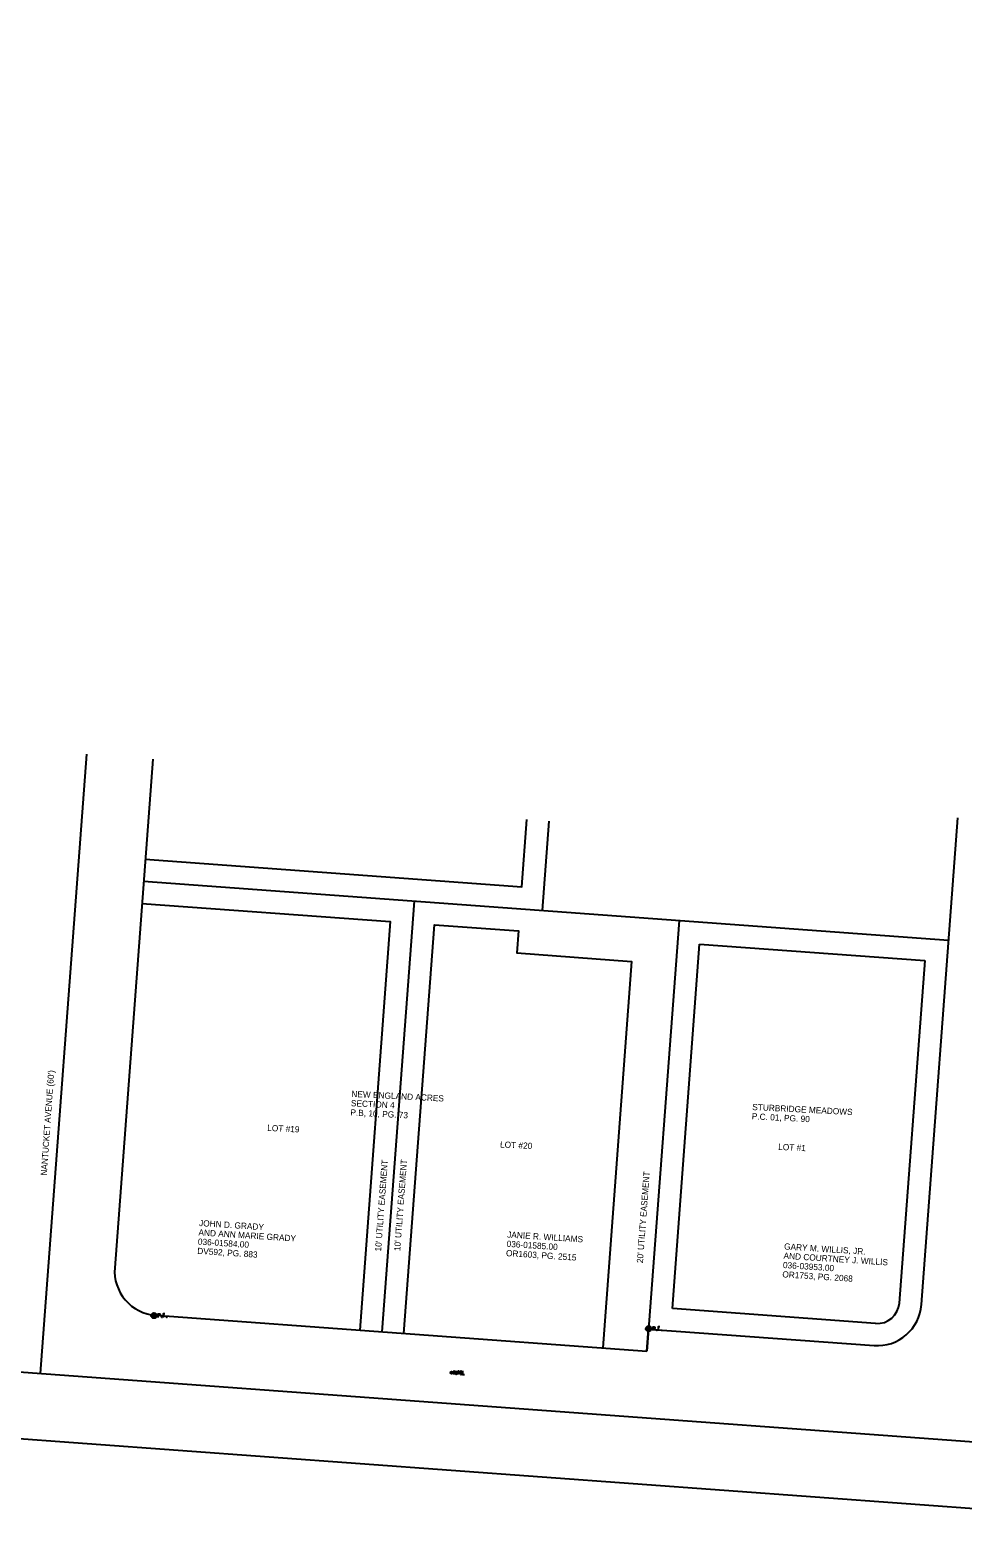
# Model space of a CAD drawing. Extents: x 1898254 to 1901377, y 701554 to 704886.
# Drawn here: x 1900647 to 1901068, y 703095 to 703775 of the extents above; entities that cross this region are included whole.
import ezdxf

# ---------------------------------------------------------------- set-up
doc = ezdxf.new("R2010")
doc.units = 0
for name, color, linetype in [('DV_X_Property_Line', 7, 'Continuous'), ('DV_X_Text', 7, 'Continuous'), ('RW_X_CL', 7, 'Continuous'), ('RW_X_Esmt_SH', 7, 'Continuous'), ('RW_X_Esmt_U', 7, 'Continuous'), ('RW_X_Fee_RW', 7, 'Continuous'), ('RW_X_Text', 7, 'Continuous'), ('SC_Scratch2', 7, 'Continuous'), ('SC_Scratch5', 7, 'Continuous'), ('SV_X_Control_Cells_Found', 7, 'Continuous'), ('SV_X_Mon_Cells_Found', 7, 'Continuous')]:
    doc.layers.add(name, color=color, linetype=linetype)

msp = doc.modelspace()

# ---------------------------------------------------------------- linework, layer by layer
at = {"layer": 'DV_X_Property_Line'}
for p, q in [((1900881.34, 703418.11), (1900878.32, 703377.77)), ((1900698.38, 703390.92), (1901061.83, 703364.35)), ((1900820.48, 703382), (1900805.96, 703187.54)), ((1900940.16, 703373.25), (1900925.64, 703178.79))]:
    msp.add_line(p, q, dxfattribs=at)
at = {"layer": 'RW_X_CL'}
for p, q in [((1900672.58, 703448.26), (1900651.7, 703168.73)), ((1899815.76, 703229.84), (1901162.17, 703131.42))]:
    msp.add_line(p, q, dxfattribs=at)
at = {"layer": 'RW_X_Esmt_SH'}
msp.add_line((1900608.03, 703141.85), (1901159.98, 703101.5), dxfattribs=at)
at = {"layer": 'RW_X_Esmt_U'}
for p, q in [((1900937.1, 703198), (1900949.39, 703362.55)), ((1900949.39, 703362.55), (1901051.12, 703355.11)), ((1901051.12, 703355.11), (1901039.57, 703200.52)), ((1901028.87, 703191.3), (1900937.1, 703198)), ((1901028.87, 703191.3), (1901028.87, 703191.3))]:
    msp.add_line(p, q, dxfattribs=at)
for points in [[(1900699.11, 703400.89), (1900869.1, 703388.47), (1900871.36, 703418.85)], [(1900697.65, 703380.95), (1900809.76, 703372.75), (1900795.98, 703188.27)], [(1900815.93, 703186.81), (1900829.71, 703371.29), (1900867.61, 703368.52), (1900866.86, 703358.55), (1900918.72, 703354.76), (1900905.69, 703180.25)]]:
    msp.add_lwpolyline(points, dxfattribs=at)
msp.add_arc((1901029.6, 703201.27), 10, 265.81918, 355.7289, dxfattribs=at)
at = {"layer": 'RW_X_Fee_RW'}
for p, q in [((1900702.5, 703446.02), (1900685.35, 703216.44)), ((1901049.54, 703199.78), (1901065.96, 703419.55)), ((1900703.84, 703195), (1900925.64, 703178.79)), ((1900925.64, 703178.79), (1900926.38, 703188.76)), ((1900926.38, 703188.76), (1901028.14, 703181.32))]:
    msp.add_line(p, q, dxfattribs=at)
for centre, start, end in [((1900705.29, 703214.95), 175.7289, 265.81918), ((1901029.6, 703201.27), 265.81918, 355.7289)]:
    msp.add_arc(centre, 20, start, end, dxfattribs=at)
at = {"layer": 'SC_Scratch2'}
msp.add_circle((1899815.76, 703229.84), 1561.35, dxfattribs=at)
at = {"layer": 'SC_Scratch5'}
for p, q in [((1900702.5, 703446.02), (1900685.35, 703216.44)), ((1901049.54, 703199.78), (1901065.96, 703419.55)), ((1900703.84, 703195), (1900925.64, 703178.79)), ((1900925.64, 703178.79), (1900926.38, 703188.76)), ((1900926.38, 703188.76), (1901028.14, 703181.32)), ((1900608.03, 703141.85), (1901159.98, 703101.5))]:
    msp.add_line(p, q, dxfattribs=at)
for centre, start, end in [((1900705.29, 703214.95), 175.7289, 265.81918), ((1901029.6, 703201.27), 265.81918, 355.7289)]:
    msp.add_arc(centre, 20, start, end, dxfattribs=at)
at = {"layer": 'SV_X_Control_Cells_Found'}
for p, q in [((1900837.1, 703169.44), (1900837.8, 703168.73)), ((1900837.1, 703168.73), (1900837.8, 703169.44))]:
    msp.add_line(p, q, dxfattribs=at)
for points in [[(1900838.54, 703168.28), (1900838.54, 703169.88), (1900839.49, 703168.28), (1900839.49, 703169.88)], [(1900839.99, 703168.28), (1900840.49, 703169.88), (1900840.98, 703168.28)], [(1900840.86, 703168.65), (1900840.11, 703168.65)], [(1900841.49, 703169.88), (1900841.89, 703169.88)], [(1900841.49, 703168.28), (1900841.89, 703168.28)], [(1900841.69, 703168.28), (1900841.69, 703169.88)], [(1900842.39, 703169.88), (1900842.39, 703168.28), (1900843.26, 703168.28)]]:
    msp.add_lwpolyline(points, dxfattribs=at)
msp.add_circle((1900837.45, 703169.09), 0.5, dxfattribs=at)
at = {"layer": 'SV_X_Mon_Cells_Found'}
for points in [[(1900705.04, 703194.06), (1900705.04, 703195.66), (1900705.57, 703195.66), (1900705.63, 703195.64), (1900705.7, 703195.62), (1900705.74, 703195.59), (1900705.77, 703195.57), (1900705.82, 703195.51), (1900705.85, 703195.44), (1900705.87, 703195.34), (1900705.87, 703195.19), (1900705.86, 703195.14), (1900705.84, 703195.06), (1900705.79, 703194.98), (1900705.75, 703194.94), (1900705.72, 703194.91), (1900705.66, 703194.89), (1900705.57, 703194.88), (1900705.04, 703194.88)], [(1900706.69, 703194.27), (1900706.74, 703194.27), (1900706.77, 703194.25), (1900706.81, 703194.19), (1900706.81, 703194.13), (1900706.77, 703194.08), (1900706.74, 703194.06), (1900706.69, 703194.06), (1900706.65, 703194.08), (1900706.62, 703194.13), (1900706.62, 703194.19), (1900706.65, 703194.25), (1900706.69, 703194.27)], [(1900708.05, 703195.66), (1900707.29, 703195.66), (1900707.29, 703194.06)], [(1900707.29, 703194.88), (1900707.83, 703194.88)], [(1900708.84, 703194.27), (1900708.89, 703194.27), (1900708.92, 703194.25), (1900708.96, 703194.19), (1900708.96, 703194.13), (1900708.92, 703194.08), (1900708.89, 703194.06), (1900708.84, 703194.06), (1900708.8, 703194.08), (1900708.77, 703194.13), (1900708.77, 703194.19), (1900708.8, 703194.25), (1900708.84, 703194.27)], [(1900928.39, 703188.12), (1900928.39, 703189.72), (1900928.92, 703189.72), (1900928.97, 703189.7), (1900929.05, 703189.68), (1900929.08, 703189.65), (1900929.12, 703189.63), (1900929.16, 703189.56), (1900929.19, 703189.5), (1900929.22, 703189.4), (1900929.22, 703189.25), (1900929.21, 703189.2), (1900929.18, 703189.12), (1900929.14, 703189.04), (1900929.1, 703189), (1900929.06, 703188.97), (1900929.01, 703188.95), (1900928.92, 703188.93), (1900928.39, 703188.93)], [(1900930.03, 703188.33), (1900930.09, 703188.33), (1900930.12, 703188.3), (1900930.15, 703188.25), (1900930.15, 703188.19), (1900930.12, 703188.14), (1900930.09, 703188.12), (1900930.03, 703188.12), (1900930, 703188.14), (1900929.97, 703188.19), (1900929.97, 703188.25), (1900930, 703188.3), (1900930.03, 703188.33)], [(1900931.4, 703189.72), (1900930.64, 703189.72), (1900930.64, 703188.12)], [(1900930.64, 703188.93), (1900931.18, 703188.93)], [(1900932.18, 703188.33), (1900932.24, 703188.33), (1900932.27, 703188.3), (1900932.3, 703188.25), (1900932.3, 703188.19), (1900932.27, 703188.14), (1900932.24, 703188.12), (1900932.18, 703188.12), (1900932.15, 703188.14), (1900932.12, 703188.19), (1900932.12, 703188.25), (1900932.15, 703188.3), (1900932.18, 703188.33)]]:
    msp.add_lwpolyline(points, dxfattribs=at)
for centre, radius in [((1900703.05, 703194.86), 1.2), ((1900703.05, 703194.86), 0.495), ((1900926.39, 703188.92), 1.2), ((1900926.39, 703188.92), 0.495)]:
    msp.add_circle(centre, radius, dxfattribs=at)

# ---------------------------------------------------------------- texts
at = {"layer": 'DV_X_Text'}
for s, rotation, p in [('NEW ENGLAND ACRES', 357.09486, (1900792.14, 703293.59)), ('SECTION 4', 357.09486, (1900791.93, 703289.4)), ('STURBRIDGE MEADOWS', 357.09486, (1900973.12, 703287.66)), ('P.B, 10, PG. 73', 357.09486, (1900791.72, 703285.2)), ('P.C. 01, PG. 90', 357.09486, (1900972.91, 703283.46)), ('LOT #19', 357.09486, (1900754.16, 703278.23)), ('LOT #20', 357.09486, (1900859.26, 703270.76)), ('LOT #1', 357.09486, (1900984.84, 703269.68)), ("10' UTILITY EASEMENT", 85.7139, (1900805.6, 703223.7)), ("10' UTILITY EASEMENT", 85.7139, (1900814.25, 703223.87)), ("20' UTILITY EASEMENT", 85.7139, (1900923.81, 703218.44)), ('JOHN D. GRADY ', 356.3351, (1900723.37, 703235.27)), ('036-01584.00', 356.3351, (1900722.83, 703226.89)), ('AND ANN MARIE GRADY', 356.3351, (1900723.1, 703231.08)), ('036-01585.00', 356.3351, (1900862.2, 703225.89)), ('JANIE R. WILLIAMS', 356.3351, (1900862.46, 703230.08)), ('DV592, PG. 883', 356.3351, (1900722.56, 703222.7)), ('OR1603, PG. 2515', 356.3351, (1900861.93, 703221.7)), ('AND COURTNEY J. WILLIS', 356.3351, (1900987.22, 703220.52)), ('GARY M. WILLIS, JR.', 356.3351, (1900987.49, 703224.71)), ('OR1753, PG. 2068', 356.3351, (1900986.69, 703212.13)), ('036-03953.00', 356.3351, (1900986.96, 703216.33))]:
    msp.add_text(s, height=2.8, rotation=rotation, dxfattribs=at).set_placement(p)
at = {"layer": 'RW_X_Text'}
msp.add_text("NANTUCKET AVENUE (60')", height=2.8, rotation=85.93252, dxfattribs=at).set_placement((1900654.7, 703257.94))

doc.saveas('drawing.dxf')
